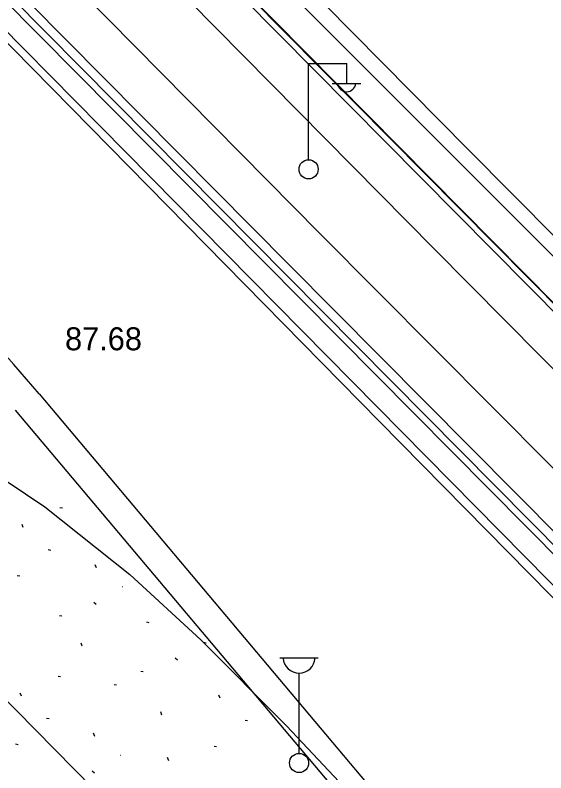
# Model space of a CAD drawing. Extents: x 412225 to 413380, y 4456471 to 4457189.
# Drawn here: x 412575.49 to 412603.2, y 4456767.84 to 4456807.42 of the extents above; entities that cross this region are included whole.
import ezdxf

# ---------------------------------------------------------------- set-up
doc = ezdxf.new("R2010")
doc.units = 0
for name, color, linetype in [('0_HALİHAZIR', 7, 'Continuous'), ('0_KADASTRO', 7, 'Continuous'), ('KALDIRIM', 7, 'Continuous'), ('Level 41', 7, 'Continuous'), ('Level 62', 7, 'Continuous')]:
    doc.layers.add(name, color=color, linetype=linetype)

msp = doc.modelspace()

# ---------------------------------------------------------------- linework, layer by layer
at = {"layer": '0_HALİHAZIR'}
for p, q in [((412590.8, 4456799.892), (412590.8, 4456804.892)), ((412590.8, 4456804.892), (412592.8, 4456804.892)), ((412592.8, 4456803.892), (412592.8, 4456804.892)), ((412592.04, 4456803.852), (412593.54, 4456803.852)), ((412589.313, 4456773.853), (412591.313, 4456773.853)), ((412590.313, 4456768.853), (412590.313, 4456773.046))]:
    msp.add_line(p, q, dxfattribs=at)
for points in [[(412644.931, 4456753.555), (412630.555, 4456767.782), (412604.684, 4456793.709), (412582.154, 4456816.287), (412559.135, 4456839.628), (412534.75, 4456864.124), (412499.888, 4456899.345), (412487.433, 4456911.736), (412459.99, 4456939.333), (412440.337, 4456959.115), (412419.902, 4456979.921), (412392.691, 4457007.039), (412362.588, 4457037.58), (412334.209, 4457066.321), (412297.701, 4457103.437), (412284.18, 4457117.149)], [(412283.985, 4457100.322), (412303.353, 4457080.961), (412332.911, 4457051.149), (412362.488, 4457021.336), (412400.253, 4456983.455), (412425.306, 4456957.949), (412451.956, 4456931.175), (412483.613, 4456899.459), (412507.045, 4456875.463), (412533.953, 4456848.693), (412570.746, 4456810.938), (412594.382, 4456786.967), (412618.72, 4456762.275), (412633.267, 4456747.178), (412636.335, 4456744.215)], [(412645.421, 4456754.062), (412629.127, 4456770.178), (412599.147, 4456800.409), (412567.615, 4456832.31), (412536.489, 4456863.396), (412502.72, 4456897.599), (412471.675, 4456928.735), (412445.148, 4456955.565), (412406.259, 4456994.837)], [(412637.165, 4456746.318), (412618.159, 4456765.78), (412589.798, 4456794.375), (412560.702, 4456823.748), (412525.834, 4456858.92), (412495.532, 4456889.87), (412469.975, 4456915.531), (412420.275, 4456965.756), (412393.731, 4456992.619)], [(412414.019, 4456980.608), (412430.818, 4456963.728), (412462.102, 4456931.987), (412481.52, 4456912.466), (412499.923, 4456893.817), (412530.253, 4456863.229), (412548.59, 4456844.546), (412567.492, 4456825.478), (412597.357, 4456795.212), (412619.629, 4456772.724)], [(412412.412, 4456976.824), (412430.58, 4456958.484), (412471.136, 4456917.576), (412494.611, 4456893.791), (412529.094, 4456859.09), (412552.718, 4456835.192), (412591.392, 4456796.015), (412615.481, 4456771.779), (412632.916, 4456754.119)], [(412635.095, 4456744.706), (412621.293, 4456758.968), (412594.514, 4456786.189), (412564.28, 4456816.959), (412527.989, 4456853.886), (412497.963, 4456883.985), (412468.818, 4456913.357), (412423.738, 4456958.933), (412408.728, 4456974.086)], [(412554.446, 4456842.344), (412574.337, 4456821.975), (412608.572, 4456787.352), (412635.895, 4456760.057), (412643.635, 4456752.216)], [(412556.602, 4456786.488), (412559.716, 4456787.076), (412562.261, 4456787.245), (412564.45, 4456787.047), (412567.217, 4456786.677), (412569.463, 4456785.953), (412571.645, 4456785.081), (412573.932, 4456783.8), (412577.036, 4456781.742), (412581.476, 4456778.207), (412585.175, 4456774.793), (412589.663, 4456770.29), (412598.445, 4456760.934), (412599.632, 4456759.571), (412599.835, 4456759.212), (412599.894, 4456758.556), (412599.816, 4456758.259), (412599.54, 4456758.025), (412598.985, 4456757.737)]]:
    msp.add_lwpolyline(points, dxfattribs=at)
for centre in [(412590.81, 4456799.367), (412590.313, 4456768.353)]:
    msp.add_circle(centre, 0.5, dxfattribs=at)
for centre, radius, start, end in [((412592.8, 4456803.895), 0.474, 184.8384, 355.1464), ((412590.313, 4456773.883), 0.837, 183.298, 356.9072)]:
    msp.add_arc(centre, radius, start, end, dxfattribs=at)
at = {"layer": '0_KADASTRO'}
msp.add_lwpolyline([(412511.64, 4456802.61), (412523.869, 4456823.705), (412617.056, 4456728.859), (412543.593, 4456703.12), (412527.466, 4456778.138), (412524.42, 4456784.89), (412522.24, 4456788.56), (412519.52, 4456792.85), (412512.99, 4456801.24)], close=True, dxfattribs=at)
at = {"layer": 'KALDIRIM'}
msp.add_line((412575.489, 4456786.792), (412598.63, 4456759.298), dxfattribs=at)
at = {"layer": 'Level 41'}
for p, q in [((412577.827, 4456781.7), (412577.953, 4456781.675)), ((412577.827, 4456781.7), (412577.953, 4456781.675)), ((412575.913, 4456780.65), (412575.848, 4456780.813)), ((412575.913, 4456780.65), (412575.848, 4456780.813)), ((412577.22, 4456779.502), (412577.346, 4456779.477)), ((412577.22, 4456779.502), (412577.346, 4456779.477)), ((412579.733, 4456778.547), (412579.67, 4456778.709)), ((412579.733, 4456778.547), (412579.67, 4456778.709)), ((412575.602, 4456778.151), (412575.728, 4456778.125)), ((412575.602, 4456778.151), (412575.728, 4456778.125)), ((412581.08, 4456777.57), (412581.089, 4456777.568)), ((412581.08, 4456777.57), (412581.089, 4456777.568)), ((412579.597, 4456776.746), (412579.723, 4456776.646)), ((412579.597, 4456776.746), (412579.723, 4456776.646)), ((412577.796, 4456776.06), (412577.922, 4456776.034)), ((412577.796, 4456776.06), (412577.922, 4456776.034)), ((412582.341, 4456775.719), (412582.467, 4456775.694)), ((412582.341, 4456775.719), (412582.467, 4456775.694)), ((412578.993, 4456774.449), (412578.93, 4456774.612)), ((412578.993, 4456774.449), (412578.93, 4456774.612)), ((412585.33, 4456774.664), (412585.455, 4456774.638)), ((412585.33, 4456774.664), (412585.455, 4456774.638)), ((412583.846, 4456773.841), (412583.972, 4456773.741)), ((412583.846, 4456773.841), (412583.972, 4456773.741)), ((412577.737, 4456772.894), (412577.863, 4456772.869)), ((412577.737, 4456772.894), (412577.863, 4456772.869)), ((412582.045, 4456773.154), (412582.171, 4456773.129)), ((412582.045, 4456773.154), (412582.171, 4456773.129)), ((412580.662, 4456772.454), (412580.788, 4456772.429)), ((412580.662, 4456772.454), (412580.788, 4456772.429)), ((412575.823, 4456771.845), (412575.758, 4456772.008)), ((412575.823, 4456771.845), (412575.758, 4456772.008)), ((412586.19, 4456771.739), (412586.126, 4456771.901)), ((412586.19, 4456771.739), (412586.126, 4456771.901)), ((412583.15, 4456770.855), (412583.086, 4456771.019)), ((412583.15, 4456770.855), (412583.086, 4456771.019)), ((412577.13, 4456770.696), (412577.256, 4456770.671)), ((412577.13, 4456770.696), (412577.256, 4456770.671)), ((412587.497, 4456770.59), (412587.623, 4456770.565)), ((412587.497, 4456770.59), (412587.623, 4456770.565)), ((412579.642, 4456769.742), (412579.58, 4456769.903)), ((412579.642, 4456769.742), (412579.58, 4456769.903)), ((412575.512, 4456769.345), (412575.638, 4456769.319)), ((412575.512, 4456769.345), (412575.638, 4456769.319)), ((412585.88, 4456769.239), (412586.006, 4456769.213)), ((412585.88, 4456769.239), (412586.006, 4456769.213)), ((412580.99, 4456768.764), (412580.999, 4456768.762)), ((412580.99, 4456768.764), (412580.999, 4456768.762)), ((412583.507, 4456768.469), (412583.444, 4456768.632)), ((412583.507, 4456768.469), (412583.444, 4456768.632)), ((412579.507, 4456767.94), (412579.633, 4456767.841)), ((412579.507, 4456767.94), (412579.633, 4456767.841))]:
    msp.add_line(p, q, dxfattribs=at)
at = {"layer": 'Level 62'}
for p, q in [((412643.265, 4456752.271), (412497.51, 4456899.572)), ((412497.295, 4456899.362), (412643.049, 4456752.063)), ((412491.172, 4456893.395), (412636.692, 4456746.295)), ((412490.887, 4456893.113), (412636.434, 4456746.08)), ((412576.737, 4456787.639), (412599.628, 4456760.441))]:
    msp.add_line(p, q, dxfattribs=at)
for points in [[(412414.019, 4456980.608), (412430.818, 4456963.728), (412462.102, 4456931.987), (412481.52, 4456912.466), (412499.923, 4456893.817), (412530.253, 4456863.229), (412548.59, 4456844.546), (412567.492, 4456825.478), (412597.357, 4456795.212), (412619.629, 4456772.724)], [(412412.412, 4456976.824), (412430.58, 4456958.484), (412471.136, 4456917.576), (412494.611, 4456893.791), (412529.094, 4456859.09), (412552.718, 4456835.192), (412591.392, 4456796.015), (412615.481, 4456771.779), (412632.916, 4456754.119)], [(412576.737, 4456787.639), (412576.086, 4456788.404), (412575.428, 4456789.163), (412574.761, 4456789.915), (412574.088, 4456790.661), (412573.407, 4456791.399), (412572.718, 4456792.131), (412572.023, 4456792.856), (412571.32, 4456793.574)]]:
    msp.add_lwpolyline(points, dxfattribs=at)

# ---------------------------------------------------------------- texts
at = {"layer": '0_HALİHAZIR'}
msp.add_text('87.68', height=1.2, dxfattribs=at).set_placement((412578.092, 4456789.913))

doc.saveas('drawing.dxf')
